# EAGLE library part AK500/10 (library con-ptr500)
CONNECTOR
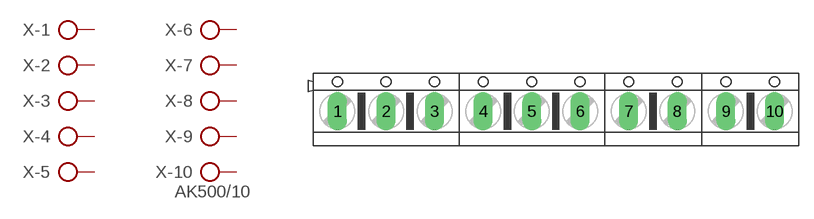
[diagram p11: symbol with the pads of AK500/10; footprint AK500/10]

Designator prefix X; gates -1=KL -2=KL -3=KL -4=KL -5=KL -6=KL -7=KL -8=KL -9=KL -10=KLV

## AK500/10 (OC_FARNELL: unknown; OC_NEWARK: unknown)  [AK500/10]
1  -1:KL  pas
2  -2:KL  pas
3  -3:KL  pas
4  -4:KL  pas
5  -5:KL  pas
6  -6:KL  pas
7  -7:KL  pas
8  -8:KL  pas
9  -9:KL  pas
10  -10:KL  pas

## Footprint AK500/10 (pad centres in mm)
CONNECTOR
drill 1.321 long: 1 -22.504,0; 2 -17.501,0; 3 -12.497,0; 4 -7.493,0; 5 -2.489,0; 6 2.489,0; 7 7.493,0; 8 12.497,0; 9 17.501,0; 10 22.504,0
